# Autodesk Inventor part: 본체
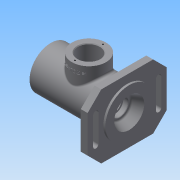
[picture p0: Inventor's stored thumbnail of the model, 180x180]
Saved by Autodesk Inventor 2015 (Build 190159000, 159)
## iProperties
Created: 2017-10
Part Number: 본체
Material: 일반
Document SubType Name: Modeling
Designer: user
Density: 1 g/cm^3
Appearance: 기본값
Author: user
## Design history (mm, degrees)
sketch "스케치1"
  geometry: L1 (-57.5, 0)-(57.5, 0); L2 (-57.5, 0)-(-57.5, 31); L3 (-57.5, 31)-(-26.5, 31); L4 (23.5, 31)-(44.5, 31); L5 (44.5, 31)-(44.5, 47); L6 (44.5, 47)-(54.5, 47); L7 (54.5, 47)-(54.5, 35); L8 (54.5, 35)-(57.5, 35); L9 (57.5, 35)-(57.5, 0); L10 (-26.5, 31)-(23.5, 31); 2 further points
  constraints: 20 end point, 5 perpendicular, 2 coincident, 2 point on line, 1 collinear, 1 horizontal, 1 midpoint, 1 vertical
  dimensions: "d0" = 115 distance of L1.start L1.end; "d1" = 31 distance of L1.start L2.end; "d7" = 10 distance of L5.end L6.end; "d9" = 3 distance of L7.end L8.end; "d19" = 35 distance of L8.end L1.end; "d37" = 16 distance of L4.end L5.end
revolve "회전1" sketch "스케치1" stored, may be unused: angle "d10" = 90 deg
sketch "스케치2"
  geometry: L1 (-58, -47)-(58, -47); L2 (58, -47)-(58, 47); L3 (58, 47)-(-58, 47); L4 (-58, 47)-(-58, -47); L5 (-58, -47)-(58, 47); L6 (58, -47)-(-58, 47); C1 r 47 at (0, 0) reference
  constraints: 12 end point, 2 parallel, 1 horizontal, 1 perpendicular
  dimensions: "d12" = 116 distance of L3.end L2.end; "d13" = 94 distance of L2.end L1.end
extrude "돌출1" join sketch "스케치2" distance "d14" = 10; taper "d15" = 0 deg
chamfer "모따기1" distance "d16" = 20; stored, may be unused: second distance "d17" = 2, angle "d18" = 45 deg
sketch "스케치3"
  geometry: L1 (-104, 7)-(-104, 47); L2 (-12, 47)-(-12, 7); L3 (-104, 47)-(-104, 7); L4 (-108, 47)-(-108, 7); L5 (-100, 7)-(-100, 47); L6 (-12, 47)-(-12, 7); L7 (-16, 47)-(-16, 7); L8 (-8, 7)-(-8, 47); A1 r 4 centre (-104, 47) between (-100, 47) and (-108, 47); A2 r 4 centre (-104, 7) between (-108, 7) and (-100, 7); A3 r 4 centre (-12, 47) between (-8, 47) and (-16, 47); A4 r 4 centre (-12, 7) between (-16, 7) and (-8, 7); 2 further points
  constraints: 20 end point, 8 point on circle, 8 tangent, 4 centre point, 4 equal length, 2 midpoint
  dimensions: "d22" = 40 distance of L1.start L1.end; "d23" = 92 distance of L1.end L2.start; "d24" = 40 distance of L2.start L2.end; "d25" = 8 diameter of A2; "d26" = 8 diameter of A4
extrude "돌출2" cut sketch "스케치3" distance "d27" = 13; taper "d28" = 0 deg
sketch "스케치4"
  geometry: C1 r 31 at (0, 0) reference
hole "구멍1" sketch "스케치4" at (0, 0) diameter "d29" = 40.376; stored, may be unused: countersink angle "d33" = 90 deg, drill point angle "d35" = 118 deg; dims "d30" = 9, "d31" = 4, "d32" = 2, "d34" = 12
sketch "스케치5"
  geometry: L1 (57.5, -35)-(57.5, 35) reference; L2 (57.5, 0)-(57.5, 22); L3 (43.5, 16)-(57.5, 22); L4 (43.5, 16)-(43.5, 12.904); L5 (36.2, 10)-(36.2, 12.5); L6 (36.2, 12.5)-(42.8, 12.5); L7 (36.2, 12.5)-(36.2, 10); L8 (36.2, 10)-(33.5, 10); L9 (33.5, 10)-(33.5, 16.5); L10 (33.5, 16.5)-(28.5, 16.5); L11 (28.5, 16.5)-(28.5, 17.5); L12 (28.5, 17.5)-(17.5, 17.5); L13 (17.5, 17.5)-(17.5, 26); L14 (17.5, 26)-(-20.5, 26); L15 (-20.5, 26)-(-20.5, 17.5); L16 (-20.5, 17.5)-(-31.5, 17.5); L17 (-31.5, 17.5)-(-31.5, 18.5); L18 (-31.5, 18.5)-(-33.25, 18.5); L19 (-33.25, 18.5)-(-33.25, 17.5); L20 (-33.25, 17.5)-(-36.5, 17.5); L21 (-36.5, 17.5)-(-36.5, 20); L22 (-36.5, 20)-(-45.5, 20); L23 (-48.5, 0)-(57.5, 0); L24 (-45.5, 20)-(-45.5, 24); L25 (-45.5, 24)-(-48.5, 24); L26 (-48.5, 24)-(-48.5, 0); L27 (42.8, 12.5)-(43.5, 12.904); 2 further points
  constraints: 52 end point, 14 perpendicular, 6 point on line, 1 horizontal, 1 midpoint
  dimensions: "d38" = 22 distance of L2.start L2.end; "d45" = 2.5 distance of L5.start L5.end; "d46" = 2.7 distance of L5.start L8.end; "d47" = 6.5 distance of L8.end L9.end; "d48" = 5 distance of L9.end L10.end; "d49" = 1 distance of L10.end L11.end; "d50" = 11 distance of L11.end L12.end; "d51" = 8.5 distance of L12.end L13.end; "d52" = 38 distance of L13.end L14.end; "d53" = 8.5 distance of L14.end L15.end; "d54" = 11 distance of L15.end L16.end; "d55" = 1 distance of L16.end L17.end; "d56" = 1.75 distance of L17.end L18.end; "d57" = 1 distance of L18.end L19.end (derived); "d58" = 3.25 distance of L19.end L20.end; "d59" = 2.5 distance of L20.end L21.end; "d60" = 9 distance of L21.end L22.end; "d88" = 4 distance of L22.end L24.end; "d89" = 3 distance of L24.end L25.end; "d92" = 30 deg angle of L6 L27
revolve "회전2" sketch "스케치5" stored, may be unused: angle "d61" = 90 deg
node "작업 평면1"
sketch "스케치6"
  geometry: L1 (57.5, 31)-(57.5, -31) reference; L2 (57.5, 0)-(1.5, 0); C1 r 25 at (1.5, 0); 1 further point
  constraints: 2 end point, 1 centre point, 1 coincident, 1 horizontal, 1 midpoint
  dimensions: "d63" = 56 distance of L2.start L2.end; "d64" = 50 diameter of C1
extrude "돌출3" join sketch "스케치6" stored distance "d65" = 13; taper "d66" = 0 deg
sketch "스케치7"
  geometry: C1 r 25 at (0, 0) reference; C2 r 16 at (0, 0)
  constraints: 1 centre point, 1 coincident
  dimensions: "d67" = 32 diameter of C2
extrude "돌출4" cut sketch "스케치7" stored distance "d68" = 13; taper "d69" = 0 deg
sketch "스케치8"
  geometry: 2 further points
hole "구멍2" sketch "스케치8" at (0, 20.5), (0, -20.5) diameter "d71" = 2.459; stored, may be unused: countersink angle "d75" = 90 deg, drill point angle "d77" = 118 deg; dims "d72" = 6, "d73" = 4, "d74" = 2, "d76" = 8
chamfer "모따기2" distance "d78" = 1; stored, may be unused: second distance "d79" = 2, angle "d80" = 45 deg
fillet "모깎기1" dims "d81" = 0.3
fillet "모깎기2" dims "d82" = 3
node "작업 평면2"
sketch "스케치9"
  geometry: L1 (-57.5, -31)-(-57.5, 31) reference; L2 (-26.5, 47)-(23.5, 47) reference; 2 further points
  constraints: 1 other
  dimensions: "d84" = 56 horizontal distance of L1.end point (-1.5, 37); "d85" = 10 distance from line of point (-1.5, 37) L2
feature "엠보싱1" sketch "스케치9" dims "d0" = 115, "d1" = 31, "d7" = 10, "d9" = 3, "d19" = 35, "d37" = 16, "d86" = 0.5, "d87" = 0
node "솔리드1"
other parameters: "d62" = 47, "d83" = 31
